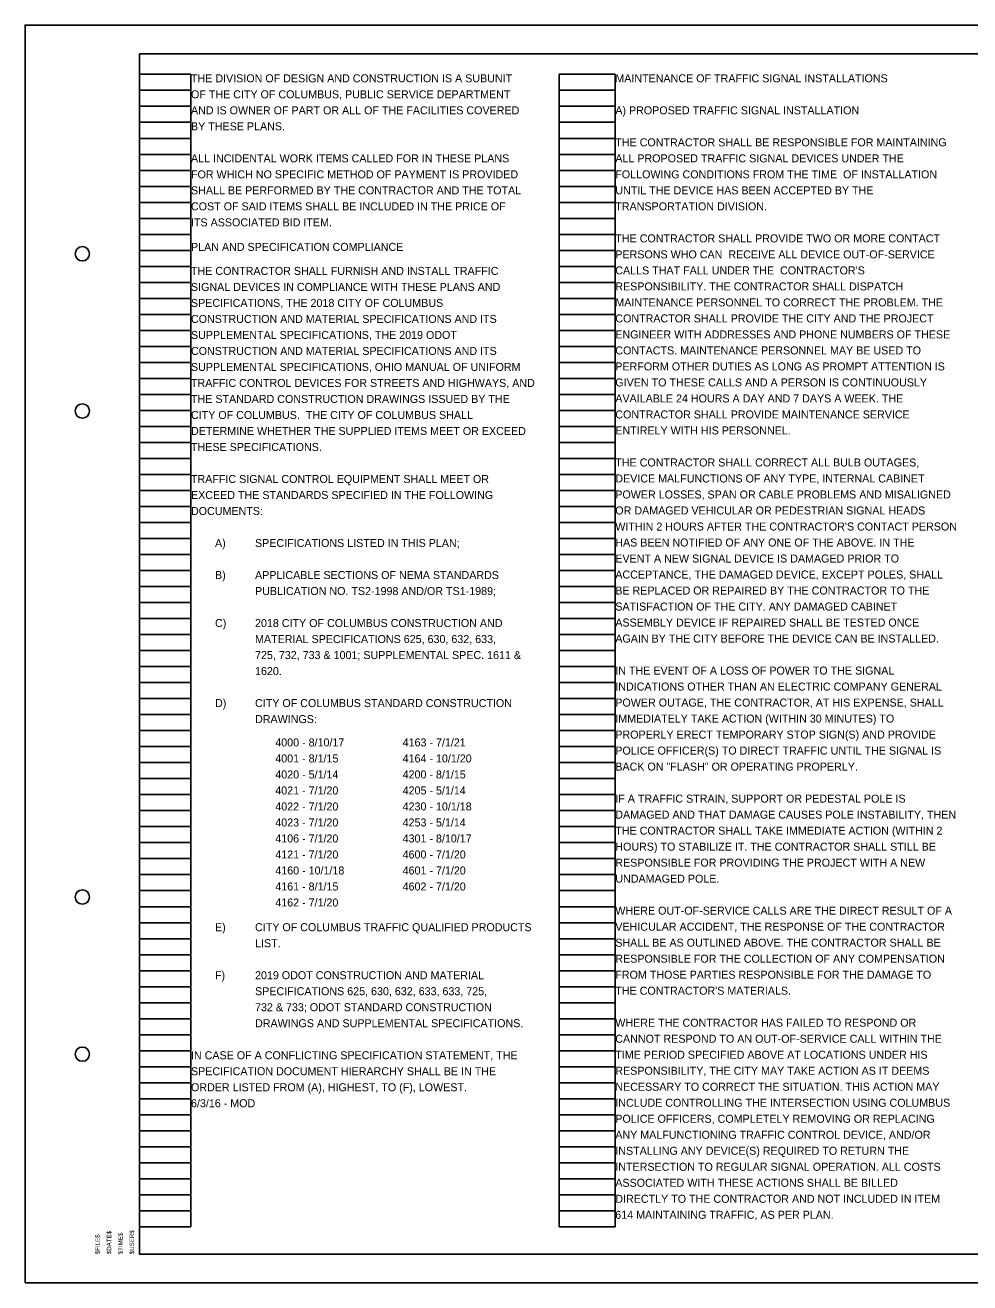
# Model space of a CAD drawing. Extents: x -62 to 50, y -16 to 14.
# Drawn here: x -0.51 to 16.01, y -7.51 to 14.49 of the extents above; entities that cross this region are included whole.
import ezdxf

# ---------------------------------------------------------------- set-up
doc = ezdxf.new("R2010")
doc.units = 0
for name, color, linetype in [('PF_P_Text', 7, 'Continuous'), ('SC_Scratch1', 7, 'Continuous'), ('SH_Cut_Line', 7, 'Continuous'), ('SH_Text', 7, 'Continuous'), ('TX_P_Misc', 7, 'Continuous')]:
    doc.layers.add(name, color=color, linetype=linetype)

msp = doc.modelspace()

# ---------------------------------------------------------------- linework, layer by layer
at = {"layer": 'PF_P_Text'}
msp.add_lwpolyline([(1.494, 13.992), (32.994, 13.992), (32.994, -7.008), (1.494, -7.008)], close=True, dxfattribs=at)
msp.add_circle((0.494, -3.508), 0.125, dxfattribs=at)
at = {"layer": 'SC_Scratch1'}
for p, q in [((1.494, -6.528), (1.494, 13.632)), ((1.494, 13.632), (2.394, 13.632)), ((2.394, -6.528), (2.394, 13.632)), ((8.834, -6.528), (8.834, 13.632)), ((8.834, 13.632), (9.814, 13.632)), ((9.814, -6.528), (9.814, 13.632)), ((1.494, 13.352), (2.394, 13.352)), ((8.834, 13.352), (9.814, 13.352)), ((1.494, 13.072), (2.394, 13.072)), ((8.834, 13.072), (9.814, 13.072)), ((1.494, 12.792), (2.394, 12.792)), ((8.834, 12.792), (9.814, 12.792)), ((1.494, 12.512), (2.394, 12.512)), ((8.834, 12.512), (9.814, 12.512)), ((1.494, 12.232), (2.394, 12.232)), ((8.834, 12.232), (9.814, 12.232)), ((1.494, 11.952), (2.394, 11.952)), ((8.834, 11.952), (9.814, 11.952)), ((1.494, 11.672), (2.394, 11.672)), ((8.834, 11.672), (9.814, 11.672)), ((1.494, 11.392), (2.394, 11.392)), ((8.834, 11.392), (9.814, 11.392)), ((1.494, 11.112), (2.394, 11.112)), ((8.834, 11.112), (9.814, 11.112)), ((1.494, 10.832), (2.394, 10.832)), ((8.834, 10.832), (9.814, 10.832)), ((1.494, 10.552), (2.394, 10.552)), ((8.834, 10.552), (9.814, 10.552)), ((1.494, 10.272), (2.394, 10.272)), ((8.834, 10.272), (9.814, 10.272)), ((1.494, 9.992), (2.394, 9.992)), ((8.834, 9.992), (9.814, 9.992)), ((1.494, 9.712), (2.394, 9.712)), ((8.834, 9.712), (9.814, 9.712)), ((1.494, 9.432), (2.394, 9.432)), ((8.834, 9.432), (9.814, 9.432)), ((1.494, 9.152), (2.394, 9.152)), ((8.834, 9.152), (9.814, 9.152)), ((1.494, 8.872), (2.394, 8.872)), ((8.834, 8.872), (9.814, 8.872)), ((1.494, 8.592), (2.394, 8.592)), ((8.834, 8.592), (9.814, 8.592)), ((1.494, 8.312), (2.394, 8.312)), ((8.834, 8.312), (9.814, 8.312)), ((1.494, 8.032), (2.394, 8.032)), ((8.834, 8.032), (9.814, 8.032)), ((1.494, 7.752), (2.394, 7.752)), ((8.834, 7.752), (9.814, 7.752)), ((1.494, 7.472), (2.394, 7.472)), ((8.834, 7.472), (9.814, 7.472)), ((1.494, 7.192), (2.394, 7.192)), ((8.834, 7.192), (9.814, 7.192)), ((1.494, 6.912), (2.394, 6.912)), ((8.834, 6.912), (9.814, 6.912)), ((1.494, 6.632), (2.394, 6.632)), ((8.834, 6.632), (9.814, 6.632)), ((1.494, 6.352), (2.394, 6.352)), ((8.834, 6.352), (9.814, 6.352)), ((1.494, 6.072), (2.394, 6.072)), ((8.834, 6.072), (9.814, 6.072)), ((1.494, 5.792), (2.394, 5.792)), ((8.834, 5.792), (9.814, 5.792)), ((1.494, 5.512), (2.394, 5.512)), ((8.834, 5.512), (9.814, 5.512)), ((1.494, 5.232), (2.394, 5.232)), ((8.834, 5.232), (9.814, 5.232)), ((1.494, 4.952), (2.394, 4.952)), ((8.834, 4.952), (9.814, 4.952)), ((1.494, 4.672), (2.394, 4.672)), ((8.834, 4.672), (9.814, 4.672)), ((1.494, 4.392), (2.394, 4.392)), ((8.834, 4.392), (9.814, 4.392)), ((1.494, 4.112), (2.394, 4.112)), ((8.834, 4.112), (9.814, 4.112)), ((1.494, 3.832), (2.394, 3.832)), ((8.834, 3.832), (9.814, 3.832)), ((1.494, 3.552), (2.394, 3.552)), ((8.834, 3.552), (9.814, 3.552)), ((1.494, 3.272), (2.394, 3.272)), ((8.834, 3.272), (9.814, 3.272)), ((1.494, 2.992), (2.394, 2.992)), ((8.834, 2.992), (9.814, 2.992)), ((1.494, 2.712), (2.394, 2.712)), ((8.834, 2.712), (9.814, 2.712)), ((1.494, 2.432), (2.394, 2.432)), ((8.834, 2.432), (9.814, 2.432)), ((1.494, 2.152), (2.394, 2.152)), ((8.834, 2.152), (9.814, 2.152)), ((1.494, 1.872), (2.394, 1.872)), ((8.834, 1.872), (9.814, 1.872)), ((1.494, 1.592), (2.394, 1.592)), ((8.834, 1.592), (9.814, 1.592)), ((1.494, 1.312), (2.394, 1.312)), ((8.834, 1.312), (9.814, 1.312)), ((1.494, 1.032), (2.394, 1.032)), ((8.834, 1.032), (9.814, 1.032)), ((1.494, 0.752), (2.394, 0.752)), ((8.834, 0.752), (9.814, 0.752)), ((1.494, 0.472), (2.394, 0.472)), ((8.834, 0.472), (9.814, 0.472)), ((1.494, 0.192), (2.394, 0.192)), ((8.834, 0.192), (9.814, 0.192)), ((1.494, -0.088), (2.394, -0.088)), ((8.834, -0.088), (9.814, -0.088)), ((1.494, -0.368), (2.394, -0.368)), ((8.834, -0.368), (9.814, -0.368)), ((1.494, -0.648), (2.394, -0.648)), ((8.834, -0.648), (9.814, -0.648)), ((1.494, -0.928), (2.394, -0.928)), ((8.834, -0.928), (9.814, -0.928)), ((1.494, -1.208), (2.394, -1.208)), ((8.834, -1.208), (9.814, -1.208)), ((1.494, -1.488), (2.394, -1.488)), ((8.834, -1.488), (9.814, -1.488)), ((1.494, -1.768), (2.394, -1.768)), ((8.834, -1.768), (9.814, -1.768)), ((1.494, -2.048), (2.394, -2.048)), ((8.834, -2.048), (9.814, -2.048)), ((1.494, -2.328), (2.394, -2.328)), ((8.834, -2.328), (9.814, -2.328)), ((1.494, -2.608), (2.394, -2.608)), ((8.834, -2.608), (9.814, -2.608)), ((1.494, -2.888), (2.394, -2.888)), ((8.834, -2.888), (9.814, -2.888)), ((1.494, -3.168), (2.394, -3.168)), ((8.834, -3.168), (9.814, -3.168)), ((1.494, -3.448), (2.394, -3.448)), ((8.834, -3.448), (9.814, -3.448)), ((1.494, -3.728), (2.394, -3.728)), ((8.834, -3.728), (9.814, -3.728)), ((1.494, -4.008), (2.394, -4.008)), ((8.834, -4.008), (9.814, -4.008)), ((1.494, -4.288), (2.394, -4.288)), ((8.834, -4.288), (9.814, -4.288)), ((1.494, -4.568), (2.394, -4.568)), ((8.834, -4.568), (9.814, -4.568)), ((1.494, -4.848), (2.394, -4.848)), ((8.834, -4.848), (9.814, -4.848)), ((1.494, -5.128), (2.394, -5.128)), ((8.834, -5.128), (9.814, -5.128)), ((1.494, -5.408), (2.394, -5.408)), ((8.834, -5.408), (9.814, -5.408)), ((1.494, -5.688), (2.394, -5.688)), ((8.834, -5.688), (9.814, -5.688)), ((1.494, -5.968), (2.394, -5.968)), ((8.834, -5.968), (9.814, -5.968)), ((1.494, -6.248), (2.394, -6.248)), ((8.834, -6.248), (9.814, -6.248)), ((1.494, -6.528), (2.394, -6.528)), ((8.834, -6.528), (9.814, -6.528)), ((-0.506, -7.508), (-0.506, -7.508))]:
    msp.add_line(p, q, dxfattribs=at)
at = {"layer": 'SH_Cut_Line'}
msp.add_lwpolyline([(-0.506, -7.508), (33.494, -7.508), (33.494, 14.492), (-0.506, 14.492)], close=True, dxfattribs=at)
at = {"layer": 'SH_Text'}
for centre in [(0.494, 10.492), (0.494, 7.742), (0.494, -0.758)]:
    msp.add_circle(centre, 0.125, dxfattribs=at)

# ---------------------------------------------------------------- texts
for s, p in [('THE DIVISION OF DESIGN AND CONSTRUCTION IS A SUBUNIT ', (2.394, 13.492)), ('MAINTENANCE OF TRAFFIC SIGNAL INSTALLATIONS ', (9.814, 13.492)), ('OF THE CITY OF COLUMBUS, PUBLIC SERVICE DEPARTMENT ', (2.394, 13.212)), ('AND IS OWNER OF PART OR ALL OF THE FACILITIES COVERED ', (2.394, 12.932)), ('A) PROPOSED TRAFFIC SIGNAL INSTALLATION', (9.814, 12.932)), ('BY THESE PLANS.', (2.394, 12.652)), ('THE CONTRACTOR SHALL BE RESPONSIBLE FOR MAINTAINING ', (9.814, 12.372)), ('ALL INCIDENTAL WORK ITEMS CALLED FOR IN THESE PLANS ', (2.394, 12.092)), ('ALL PROPOSED TRAFFIC SIGNAL DEVICES UNDER THE ', (9.814, 12.092)), ('FOR WHICH NO SPECIFIC METHOD OF PAYMENT IS PROVIDED ', (2.394, 11.812)), ('FOLLOWING CONDITIONS FROM THE TIME  OF INSTALLATION ', (9.814, 11.812)), ('SHALL BE PERFORMED BY THE CONTRACTOR AND THE TOTAL ', (2.394, 11.532)), ('UNTIL THE DEVICE HAS BEEN ACCEPTED BY THE ', (9.814, 11.532)), ('COST OF SAID ITEMS SHALL BE INCLUDED IN THE PRICE OF ', (2.394, 11.252)), ('TRANSPORTATION DIVISION. ', (9.814, 11.252)), ('ITS ASSOCIATED BID ITEM.', (2.394, 10.972)), ('THE CONTRACTOR SHALL PROVIDE TWO OR MORE CONTACT ', (9.814, 10.692)), ('PLAN AND SPECIFICATION COMPLIANCE ', (2.394, 10.543)), ('PERSONS WHO CAN  RECEIVE ALL DEVICE OUT-OF-SERVICE ', (9.814, 10.412)), ('THE CONTRACTOR SHALL FURNISH AND INSTALL TRAFFIC ', (2.394, 10.123)), ("CALLS THAT FALL UNDER THE  CONTRACTOR'S ", (9.814, 10.132)), ('SIGNAL DEVICES IN COMPLIANCE WITH THESE PLANS AND ', (2.394, 9.843)), ('RESPONSIBILITY. THE CONTRACTOR SHALL DISPATCH  ', (9.814, 9.852)), ('SPECIFICATIONS, THE 2018 CITY OF COLUMBUS ', (2.394, 9.563)), ('MAINTENANCE PERSONNEL TO CORRECT THE PROBLEM. THE ', (9.814, 9.572)), ('CONSTRUCTION AND MATERIAL SPECIFICATIONS AND ITS ', (2.394, 9.283)), ('CONTRACTOR SHALL PROVIDE THE CITY AND THE PROJECT ', (9.814, 9.292)), ('SUPPLEMENTAL SPECIFICATIONS, THE 2019 ODOT ', (2.394, 9.003)), ('ENGINEER WITH ADDRESSES AND PHONE NUMBERS OF THESE ', (9.814, 9.012)), ('CONSTRUCTION AND MATERIAL SPECIFICATIONS AND ITS ', (2.394, 8.723)), ('CONTACTS. MAINTENANCE PERSONNEL MAY BE USED TO ', (9.814, 8.732)), ('SUPPLEMENTAL SPECIFICATIONS, OHIO MANUAL OF UNIFORM ', (2.394, 8.443)), ('PERFORM OTHER DUTIES AS LONG AS PROMPT ATTENTION IS ', (9.814, 8.452)), ('TRAFFIC CONTROL DEVICES FOR STREETS AND HIGHWAYS, AND ', (2.394, 8.163)), ('GIVEN TO THESE CALLS AND A PERSON IS CONTINUOUSLY ', (9.814, 8.172)), ('THE STANDARD CONSTRUCTION DRAWINGS ISSUED BY THE ', (2.394, 7.883)), ('AVAILABLE 24 HOURS A DAY AND 7 DAYS A WEEK. THE ', (9.814, 7.892)), ('CITY OF COLUMBUS.  THE CITY OF COLUMBUS SHALL ', (2.394, 7.603)), ('CONTRACTOR SHALL PROVIDE MAINTENANCE SERVICE ', (9.814, 7.612)), ('DETERMINE WHETHER THE SUPPLIED ITEMS MEET OR EXCEED ', (2.394, 7.323)), ('ENTIRELY WITH HIS PERSONNEL.', (9.814, 7.332)), ('THESE SPECIFICATIONS.', (2.394, 7.043)), ('THE CONTRACTOR SHALL CORRECT ALL BULB OUTAGES, ', (9.814, 6.772)), ('TRAFFIC SIGNAL CONTROL EQUIPMENT SHALL MEET OR ', (2.394, 6.483)), ('DEVICE MALFUNCTIONS OF ANY TYPE, INTERNAL CABINET ', (9.814, 6.492)), ('EXCEED THE STANDARDS SPECIFIED IN THE FOLLOWING ', (2.394, 6.203)), ('POWER LOSSES, SPAN OR CABLE PROBLEMS AND MISALIGNED ', (9.814, 6.212)), ('DOCUMENTS:', (2.394, 5.923)), ('OR DAMAGED VEHICULAR OR PEDESTRIAN SIGNAL HEADS ', (9.814, 5.932)), ("WITHIN 2 HOURS AFTER THE CONTRACTOR'S CONTACT PERSON ", (9.814, 5.652)), ('A)', (2.814, 5.363)), ('SPECIFICATIONS LISTED IN THIS PLAN;', (3.514, 5.363)), ('HAS BEEN NOTIFIED OF ANY ONE OF THE ABOVE. IN THE ', (9.814, 5.372)), ('EVENT A NEW SIGNAL DEVICE IS DAMAGED PRIOR TO ', (9.814, 5.092)), ('B)', (2.814, 4.803)), ('APPLICABLE SECTIONS OF NEMA STANDARDS ', (3.514, 4.803)), ('ACCEPTANCE, THE DAMAGED DEVICE, EXCEPT POLES, SHALL ', (9.814, 4.812)), ('PUBLICATION NO. TS2-1998 AND/OR TS1-1989;', (3.514, 4.523)), ('BE REPLACED OR REPAIRED BY THE CONTRACTOR TO THE ', (9.814, 4.532)), ('SATISFACTION OF THE CITY. ANY DAMAGED CABINET ', (9.814, 4.252)), ('C)', (2.814, 3.963)), ('2018 CITY OF COLUMBUS CONSTRUCTION AND ', (3.514, 3.963)), ('ASSEMBLY DEVICE IF REPAIRED SHALL BE TESTED ONCE ', (9.814, 3.972)), ('MATERIAL SPECIFICATIONS 625, 630, 632, 633, ', (3.514, 3.683)), ('AGAIN BY THE CITY BEFORE THE DEVICE CAN BE INSTALLED.', (9.814, 3.692)), ('725, 732, 733 & 1001; SUPPLEMENTAL SPEC. 1611 & ', (3.514, 3.403)), ('1620.  ', (3.514, 3.123)), ('IN THE EVENT OF A LOSS OF POWER TO THE SIGNAL ', (9.814, 3.132)), ('INDICATIONS OTHER THAN AN ELECTRIC COMPANY GENERAL ', (9.814, 2.852)), ('D)', (2.814, 2.563)), ('CITY OF COLUMBUS STANDARD CONSTRUCTION ', (3.514, 2.563)), ('POWER OUTAGE, THE CONTRACTOR, AT HIS EXPENSE, SHALL ', (9.814, 2.572)), ('DRAWINGS:', (3.514, 2.283)), ('IMMEDIATELY TAKE ACTION (WITHIN 30 MINUTES) TO ', (9.814, 2.292)), ('4000 - 8/10/17', (3.868, 1.875)), ('4163 - 7/1/21', (6.095, 1.875)), ('PROPERLY ERECT TEMPORARY STOP SIGN(S) AND PROVIDE ', (9.814, 2.012)), ('POLICE OFFICER(S) TO DIRECT TRAFFIC UNTIL THE SIGNAL IS ', (9.814, 1.732)), ('4001 - 8/1/15', (3.868, 1.595)), ('4164 - 10/1/20', (6.095, 1.595)), ('BACK ON "FLASH" OR OPERATING PROPERLY.', (9.814, 1.452)), ('4020 - 5/1/14', (3.868, 1.315)), ('4200 - 8/1/15', (6.095, 1.315)), ('4021 - 7/1/20', (3.868, 1.035)), ('4205 - 5/1/14', (6.095, 1.035)), ('4022 - 7/1/20', (3.868, 0.755)), ('4230 - 10/1/18', (6.095, 0.755)), ('IF A TRAFFIC STRAIN, SUPPORT OR PEDESTAL POLE IS ', (9.814, 0.892)), ('DAMAGED AND THAT DAMAGE CAUSES POLE INSTABILITY, THEN ', (9.814, 0.612)), ('4023 - 7/1/20', (3.868, 0.475)), ('4253 - 5/1/14', (6.095, 0.475)), ('THE CONTRACTOR SHALL TAKE IMMEDIATE ACTION (WITHIN 2 ', (9.814, 0.332)), ('4106 - 7/1/20', (3.868, 0.195)), ('4301 - 8/10/17', (6.095, 0.195)), ('4121 - 7/1/20', (3.868, -0.085)), ('4600 - 7/1/20', (6.095, -0.085)), ('HOURS) TO STABILIZE IT. THE CONTRACTOR SHALL STILL BE ', (9.814, 0.052)), ('4160 - 10/1/18', (3.868, -0.365)), ('4601 - 7/1/20', (6.095, -0.365)), ('RESPONSIBLE FOR PROVIDING THE PROJECT WITH A NEW ', (9.814, -0.228)), ('UNDAMAGED POLE.', (9.814, -0.508)), ('4161 - 8/1/15', (3.868, -0.645)), ('4602 - 7/1/20', (6.095, -0.645)), ('4162 - 7/1/20', (3.868, -0.925)), ('WHERE OUT-OF-SERVICE CALLS ARE THE DIRECT RESULT OF A ', (9.814, -1.068)), ('E) ', (2.814, -1.357)), ('CITY OF COLUMBUS TRAFFIC QUALIFIED PRODUCTS ', (3.514, -1.357)), ('VEHICULAR ACCIDENT, THE RESPONSE OF THE CONTRACTOR ', (9.814, -1.348)), ('LIST.', (3.514, -1.637)), ('SHALL BE AS OUTLINED ABOVE. THE CONTRACTOR SHALL BE ', (9.814, -1.628)), ('RESPONSIBLE FOR THE COLLECTION OF ANY COMPENSATION ', (9.814, -1.908)), ('F) ', (2.814, -2.197)), ('2019 ODOT CONSTRUCTION AND MATERIAL ', (3.514, -2.197)), ('FROM THOSE PARTIES RESPONSIBLE FOR THE DAMAGE TO ', (9.814, -2.188)), ('SPECIFICATIONS 625, 630, 632, 633, 633, 725, ', (3.514, -2.477)), ("THE CONTRACTOR'S MATERIALS.", (9.814, -2.468)), ('732 & 733; ODOT STANDARD CONSTRUCTION ', (3.514, -2.757)), ('DRAWINGS AND SUPPLEMENTAL SPECIFICATIONS.', (3.514, -3.037)), ('WHERE THE CONTRACTOR HAS FAILED TO RESPOND OR ', (9.814, -3.028)), ('CANNOT RESPOND TO AN OUT-OF-SERVICE CALL WITHIN THE ', (9.814, -3.308)), ('IN CASE OF A CONFLICTING SPECIFICATION STATEMENT, THE ', (2.394, -3.597)), ('TIME PERIOD SPECIFIED ABOVE AT LOCATIONS UNDER HIS ', (9.814, -3.588)), ('SPECIFICATION DOCUMENT HIERARCHY SHALL BE IN THE ', (2.394, -3.877)), ('RESPONSIBILITY, THE CITY MAY TAKE ACTION AS IT DEEMS ', (9.814, -3.868)), ('ORDER LISTED FROM (A), HIGHEST, TO (F), LOWEST.', (2.394, -4.157)), ('NECESSARY TO CORRECT THE SITUATION. THIS ACTION MAY ', (9.814, -4.148)), ('6/3/16 - MOD', (2.394, -4.437)), ('INCLUDE CONTROLLING THE INTERSECTION USING COLUMBUS ', (9.814, -4.428)), ('POLICE OFFICERS, COMPLETELY REMOVING OR REPLACING ', (9.814, -4.708)), ('ANY MALFUNCTIONING TRAFFIC CONTROL DEVICE, AND/OR ', (9.814, -4.988)), ('INSTALLING ANY DEVICE(S) REQUIRED TO RETURN THE ', (9.814, -5.268)), ('INTERSECTION TO REGULAR SIGNAL OPERATION. ALL COSTS ', (9.814, -5.548)), ('ASSOCIATED WITH THESE ACTIONS SHALL BE BILLED ', (9.814, -5.828)), ('DIRECTLY TO THE CONTRACTOR AND NOT INCLUDED IN ITEM ', (9.814, -6.108)), ('614 MAINTAINING TRAFFIC, AS PER PLAN.', (9.814, -6.388))]:
    msp.add_text(s, height=0.14, dxfattribs=at).set_placement(p)
at = {"layer": 'TX_P_Misc'}
for s, p in [('$FILE$', (0.799, -7.008)), ('$DATE$', (0.999, -7.008)), ('$TIME$', (1.199, -7.008)), ('$USER$', (1.399, -7.008))]:
    msp.add_text(s, height=0.078, rotation=90, dxfattribs=at).set_placement(p)

doc.saveas('drawing.dxf')
